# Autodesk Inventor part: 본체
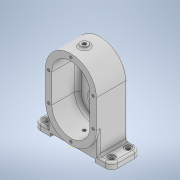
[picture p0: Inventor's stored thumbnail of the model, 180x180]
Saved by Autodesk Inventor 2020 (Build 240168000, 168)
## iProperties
Created: 2021-05
Part Number: 본체
Material: 일반
Document SubType Name: Modeling
Designer: Owner
Density: 1 g/cm^3
Appearance: 기본값
Author: Owner
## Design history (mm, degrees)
sketch "스케치2"
  geometry: L1 (0, 22.5)-(0, -22.5); L2 (-40, 22.5)-(-40, -22.5); L3 (40, -22.5)-(40, 22.5); A1 r 40 centre (0, 22.5) between (40, 22.5) and (-40, 22.5); A2 r 40 centre (0, -22.5) between (-40, -22.5) and (40, -22.5); 2 further points
  constraints: 8 end point, 4 point on circle, 4 tangent, 2 centre point, 1 coincident, 1 midpoint, 1 parallel, 1 vertical
  dimensions: "d3" = 40 radius of A1; "d4" = 45 distance of L1.end L1.start
extrude "돌출1" new body sketch "스케치2" distance "d5" = 49; taper "d6" = 0 deg
sketch "스케치3"
  geometry: L1 (0, 22.5)-(0, -22.5); L2 (-30, 22.5)-(-30, -22.5); L3 (30, -22.5)-(30, 22.5); A1 r 30 centre (0, 22.5) between (30, 22.5) and (-30, 22.5); A2 r 30 centre (0, -22.5) between (-30, -22.5) and (30, -22.5); 2 further points
  constraints: 8 end point, 4 point on circle, 4 tangent, 2 centre point, 1 coincident, 1 midpoint, 1 parallel, 1 vertical
  dimensions: "d7" = 30 radius of A1; "d8" = 45 distance of L1.end L1.start
extrude "돌출2" cut sketch "스케치3" distance "d9" = 41; taper "d10" = 0 deg
sketch "스케치4"
  geometry: L1 (-30, -22.5)-(-30, 22.5) reference; L2 (30, 22.5)-(30, -22.5) reference; L3 (-30, -22.5)-(-30, 22.5) reference; C1 r 10 at (0, -22.5); C2 r 14 at (0, -22.5); A1 r 30 centre (0, -22.5) between (-30, -22.5) and (30, -22.5) reference; A2 r 30 centre (0, -22.5) between (-30, -22.5) and (30, -22.5) reference; A3 r 30 centre (0, 22.5) between (30, 22.5) and (-30, 22.5) reference; 1 further point
  constraints: 2 centre point, 2 coincident
  dimensions: "d11" = 28 diameter of C2; "d12" = 20 diameter of C1
  node "투영된 루프1"
sketch "스케치5"
  geometry: C1 r 11 at (0, 22.5); C2 r 14 at (0, 22.5); 1 further point
  constraints: 2 centre point, 1 coincident
  dimensions: "d13" = 22.5 distance of point (0, 0) C1.centre; "d14" = 22 diameter of C1; "d15" = 28 diameter of C2
extrude "돌출3" cut sketch "스케치5" distance "d16" = 41; taper "d17" = 0 deg
extrude "돌출4" join sketch "스케치5" distance "d18" = 8; taper "d19" = 0 deg
extrude "돌출9" cut sketch "스케치5" distance "d32" = 8; taper "d33" = 0 deg
sketch "스케치9"
  geometry: 1 further point
sketch "스케치10"
  geometry: L1 (0, 22.5)-(0, -22.5); L2 (-26, 22.5)-(-26, -22.5); L3 (26, -22.5)-(26, 22.5); A1 r 40 centre (0, 22.5) between (40, 22.5) and (-40, 22.5) reference; A2 r 40 centre (0, -22.5) between (-40, -22.5) and (40, -22.5) reference; A3 r 26 centre (0, 22.5) between (26, 22.5) and (-26, 22.5); A4 r 26 centre (0, -22.5) between (-26, -22.5) and (26, -22.5); 2 further points
  constraints: 8 end point, 4 point on circle, 4 tangent, 2 centre point, 1 midpoint, 1 parallel, 1 vertical
  dimensions: "d41" = 26 radius of A3
extrude "돌출13" join sketch "스케치10" distance "d42" = 11; taper "d43" = 0 deg
sketch "스케치11"
  geometry: L1 (-26, -22.5)-(-26, 22.5) reference; L2 (-26, -7.5)-(26, -7.5); L3 (26, -22.5)-(26, 22.5) reference; A1 r 26 centre (0, 22.5) between (26, 22.5) and (-26, 22.5) reference; 1 further point
  constraints: 2 end point, 2 point on line, 1 horizontal
  dimensions: "d44" = 30 distance from line of L2 A1.centre
extrude "돌출14" cut sketch "스케치11" distance "d45" = 3; taper "d46" = 0 deg
extrude "돌출15" cut sketch "스케치5" distance "d47" = 54.25; taper "d48" = 0 deg
sketch "스케치12"
  geometry: C1 r 11 at (0, 22.5) reference; C2 r 14 at (0, 22.5); 1 further point
  constraints: 1 centre point, 1 coincident
  dimensions: "d49" = 28 diameter of C2
extrude "돌출16" cut sketch "스케치12" distance "d50" = 3; taper "d51" = 0 deg
extrude "돌출17" cut sketch "스케치4" distance "d52" = 12; taper "d53" = 0 deg
extrude "돌출18" cut sketch "스케치4" distance "d54" = 8; taper "d55" = 0 deg
sketch "스케치13"
  geometry: L1 (0, 22.5)-(0, -22.5); L2 (-35, 22.5)-(-35, -22.5); L3 (35, -22.5)-(35, 22.5); C1 r 11 at (0, 22.5) reference; A1 r 40 centre (0, 22.5) between (40, 22.5) and (-40, 22.5) reference; A2 r 40 centre (0, -22.5) between (-40, -22.5) and (40, -22.5) reference; A3 r 35 centre (0, 22.5) between (35, 22.5) and (-35, 22.5); A4 r 35 centre (0, -22.5) between (-35, -22.5) and (35, -22.5); 8 further points
  constraints: 8 end point, 6 point on circle, 4 coincident, 4 tangent, 2 centre point, 1 midpoint, 1 parallel, 1 vertical
  dimensions: "d56" = 35 radius of A3
hole "구멍1" sketch "스케치13" at (-35, 22.5), (35, 22.5), (0, 57.5), (-35, -22.5), (35, -22.5), (0, -57.5) diameter "d57" = 3.242; stored, may be unused: countersink angle "d61" = 90 deg, drill point angle "d63" = 118 deg; dims "d58" = 8, "d59" = 4, "d60" = 2, "d62" = 10
chamfer "모따기1" distance "d64" = 0.4; stored, may be unused: second distance "d65" = 2, angle "d66" = 45 deg
sketch "스케치14" dims "d67" = 40
  geometry: C1 r 11 at (0, 22.5) reference; 3 further points
  constraints: 1 coincident, 1 vertical alignment, 2 other
hole "구멍2" sketch "스케치14" at (0, 42.5) diameter "d68" = 3.242; stored, may be unused: countersink angle "d72" = 90 deg, drill point angle "d74" = 118 deg; dims "d69" = 8, "d70" = 4, "d71" = 2, "d73" = 10
chamfer "모따기2" distance "d75" = 0.4; stored, may be unused: second distance "d76" = 2, angle "d77" = 45 deg
node "작업 평면1"
sketch "스케치15"
  geometry: L1 (40, 0)-(-40, 0) reference; L2 (0, -75.608)-(0, 31.193); C1 r 6 at (0, -21); 1 further point
  constraints: 2 end point, 2 point on line, 1 centre point, 1 vertical
  dimensions: "d84" = 21 distance from line of L1 C1.centre; "d85" = 12 diameter of C1
extrude "돌출19" join sketch "스케치15" stored distance "d86" = 8; taper "d87" = 0 deg
sketch "스케치16"
  geometry: 2 further points
hole "구멍3" sketch "스케치16" at (0, 0) diameter "d88" = 4.917; stored, may be unused: countersink angle "d92" = 90 deg, drill point angle "d94" = 118 deg; dims "d89" = 12, "d90" = 4, "d91" = 2, "d93" = 60.25
chamfer "모따기3" distance "d95" = 0.6; stored, may be unused: second distance "d96" = 2, angle "d97" = 45 deg
node "작업 평면2"
sketch "스케치17"
  geometry: L1 (-61, 28)-(-35, 28); L2 (-35, 28)-(-35, -18); L3 (-35, -18)-(-61, -18); L4 (-61, -18)-(-61, 28); L5 (-40, -21)-(40, -21) reference; L6 (0, 97.296)-(0, -92.171); L7 (61, 28)-(35, 28); L8 (35, 28)-(35, -18); L9 (35, -18)-(61, -18); L10 (61, -18)-(61, 28); C1 r 3.058 at (0, 0) reference; 1 further point
  constraints: 18 end point, 4 symmetric about line, 2 parallel, 1 horizontal, 1 perpendicular, 1 point on line, 1 vertical
  dimensions: "d99" = 46 distance of L3.end L1.start; "d100" = 3 distance between parallel lines of L5 L3; "d101" = 122 distance between parallel lines of L10 L4; "d102" = 70 distance between parallel lines of L8 L2
extrude "돌출20" join sketch "스케치17" distance "d103" = 10; taper "d104" = 0 deg
sketch "스케치18"
  geometry: L1 (-40, -22.5)-(-40, -59.5); L2 (-35, -59.5)-(-61, -59.5) reference; L3 (40, -22.5)-(40, -59.5); L4 (-35, -69.5)-(-35, -59.5) reference; L5 (35, -69.5)-(35, -59.5) reference; L6 (-35, -64.5)-(35, -64.5); L7 (35, -69.5)-(61, -69.5) reference; L8 (-61, -59.5)-(-35, -59.5) reference; L9 (-40, -59.5)-(-35, -59.5); L10 (-35, -59.5)-(-35, -64.5); L11 (35, -64.5)-(35, -59.5); L12 (35, -59.5)-(40, -59.5); L13 (61, -59.5)-(35, -59.5) reference; A1 r 40 centre (0, -22.5) between (-40, -22.5) and (40, -22.5) reference; 1 further point
  constraints: 14 end point, 2 collinear, 2 midpoint, 2 perpendicular, 2 vertical, 1 horizontal, 1 point on line
  dimensions: "d105" = 5 distance between parallel lines of L7 L6
extrude "돌출21" join sketch "스케치18" distance "d106" = 46; taper "d107" = 0 deg
fillet "모깎기1" dims "d108" = 10
sketch "스케치19"
  geometry: L1 (-77.597, 5)-(73.373, 5); C1 r 5.5 at (-51, 18); C2 r 5.5 at (-51, -8); C3 r 5.5 at (51, -8); C4 r 5.5 at (51, 18); C5 r 3.3 at (-51, -8); C6 r 5.5 at (-51, 18); C7 r 3.3 at (-51, 18); A1 r 10 centre (-51, 18) between (-51, 28) and (-61, 18) reference; A2 r 10 centre (-51, -8) between (-61, -8) and (-51, -18) reference; A3 r 10 centre (51, -8) between (51, -18) and (61, -8) reference; A4 r 10 centre (51, 18) between (61, 18) and (51, 28) reference; 2 further points
  constraints: 7 centre point, 7 coincident, 2 end point, 2 symmetric about line, 1 horizontal, 1 other
  dimensions: "d109" = 11 diameter of C2; "d110" = 11 diameter of C1; "d111" = 11 diameter of C3; "d112" = 11 diameter of C4; "d113" = 6.6 diameter of C5; "d118" = 6.6 diameter of C7
extrude "돌출22" cut sketch "스케치19" distance "d114" = 2; taper "d115" = 0 deg
extrude "돌출23" cut sketch "스케치19" distance "d116" = 27.5; taper "d117" = 0 deg
extrude "돌출24" cut sketch "스케치19" distance "d119" = 1; taper "d120" = 0 deg
extrude "돌출25" cut sketch "스케치19" distance "d121" = 14.5; taper "d122" = 0 deg
sketch "스케치20"
  geometry: 1 further point
sketch "스케치21"
  geometry: C1 r 3.058 at (35, 28) reference; C2 r 6 at (35, 28); 2 further points
  constraints: 2 coincident, 1 centre point
  dimensions: "d123" = 12 diameter of C2
extrude "돌출26" cut sketch "스케치21" distance "d124" = 1; taper "d125" = 0 deg
sketch "스케치22"
  geometry: C1 r 3.058 at (0, 0) reference; 2 further points
  constraints: 1 coincident
hole "구멍4" sketch "스케치22" at (0, 0) diameter "d126" = 4.917; stored, may be unused: countersink angle "d130" = 90 deg, drill point angle "d132" = 118 deg; dims "d127" = 12, "d128" = 4, "d129" = 2, "d131" = 9.75
fillet "모깎기2" dims "d133" = 3
fillet "모깎기3" dims "d134" = 3
fillet "모깎기4" dims "d135" = 5
chamfer "모따기4" distance "d136" = 1; stored, may be unused: second distance "d137" = 2, angle "d138" = 45 deg
chamfer "모따기5" distance "d139" = 1; stored, may be unused: second distance "d140" = 2, angle "d141" = 45 deg
sketch "스케치23"
  geometry: 1 further point
sketch "스케치24"
  geometry: L1 (-8.882, -57.5)-(11.523, -57.5); L2 (-35, -64.5)-(35, -64.5) reference; L3 (35, -69.5)-(51, -69.5) reference; L4 (-16.731, -54.975)-(15.58, -54.975); L5 (15.58, -54.975)-(15.58, -59.778); L6 (15.58, -59.778)-(-16.731, -59.778); L7 (-16.731, -59.778)-(-16.731, -54.975); 1 further point
  constraints: 2 end point, 1 horizontal, 2 other
  dimensions: "d143" = 12 distance between parallel lines of L3 L1
feature "엠보싱1" sketch "스케치24" dims "d144" = 1, "d145" = 0
node "솔리드1"
pattern_circular "원형 패턴1" dims angle "d79" = 360 deg
mirror "미러1"
mirror "미러2"
feature "A9D066F2-1C7D-4E18-AEED-F7BC21143FA4" dims "d57" = 3.242, "d58" = 8, "d59" = 4, "d60" = 2, "d61" = 90 deg, "d62" = 10, "d63" = 118 deg
other parameters: "d81" = 65.5, "d98" = -135
